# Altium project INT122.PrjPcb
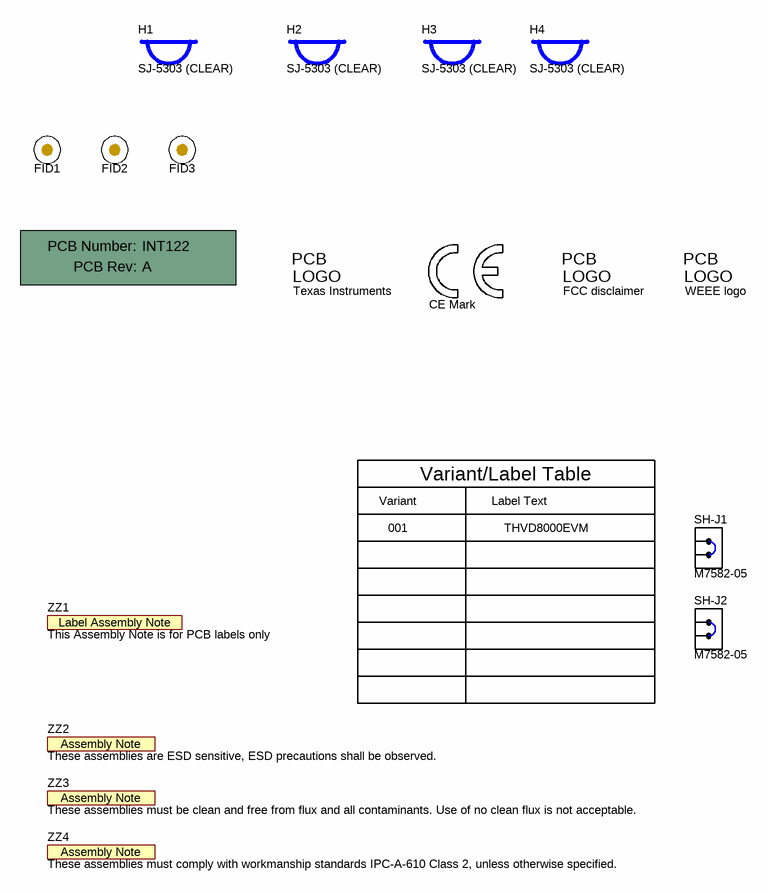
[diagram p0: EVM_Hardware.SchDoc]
CopyrightYear: 2020; PCB_Layout: A0866568; PCB_Rev: A; PRJ_Customer: Public Release; PRJ_Engineer: A0866568; PRJ_Number: INT122; PRJ_Title: THVD8000EVM; SCH_Rev: A; TechSupport: http://www.ti.com/support; TID: NA
2 sheets, 95 parts. Net scope: global (net labels, ports and power ports of the same name join across sheets).
Board file: INT122.PcbDoc
Sheets:
  EVM_Hardware.SchDoc
  INT122.SchDoc

## Sheet EVM_Hardware.SchDoc
size 431 x 279 mm; Date: Not shown in title block; ApprovedBy: Not shown in title block; CheckedBy: Not shown in title block; Author: Not shown in title block; CompanyName: Not shown in title block; Engineer: Not shown in title block; Organization: Not shown in title block; Address1: Not shown in title block; Address2: Not shown in title block; Address3: Not shown in title block; Address4: Not shown in title block; DocumentNumber: 1; Revision: Use project parameter SCH_Rev; SheetNumber: 1; SheetTotal: 2; PageSetup: Record=PageOptions¦CenterHorizontal=True¦CenterVertical=True¦PrintScale=1.00¦XCorrection=1.00¦YCorrection=1.00¦PrintKind=0¦BorderSize=5000000¦LeftOffset=0¦BottomOffset=0¦Orientation=2¦PaperLength=1000¦PaperWidth=1000¦Scale=100¦PaperSource=15¦PrintQuality=600¦MediaType=1¦DitherType=10¦PaperKind=Letter¦PrintScaleMode=1

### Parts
!PCB?  Printed Circuit Board  (value not drawn)  (mechanical)
FID1  Fiducial  [Fiducial10-20]  (value not drawn)
FID2  Fiducial  [Fiducial10-20]  (value not drawn)
FID3  Fiducial  [Fiducial10-20]  (value not drawn)
H1  SJ-5303 (CLEAR)  [Bumpon_SJ5003Transparent]
H2  SJ-5303 (CLEAR)  [Bumpon_SJ5003Transparent]
H3  SJ-5303 (CLEAR)  [Bumpon_SJ5003Transparent]
H4  SJ-5303 (CLEAR)  [Bumpon_SJ5003Transparent]
Logo1  Texas Instruments  [TI_Stacked_Overlay_Small]  (no BOM)
Logo2  CE Mark  [CE_Mark_5mm]  (no BOM)
Logo3  FCC disclaimer  [FCC_disclaimer]  (no BOM)
Logo4  WEEE logo  [WEEE_Minimum]  (no BOM)
SH-J1  M7582-05  [Harwin_M7582-05]
SH-J2  M7582-05  [Harwin_M7582-05]
ZZ1  This Assembly Note is for PCB labels only  [AssemblyNoteLabel]  (no BOM)
ZZ2  These assemblies are ESD sensitive, ESD precautions shall be observed.  [AssemblyNote]  (no BOM)
ZZ3  These assemblies must be clean and free from flux and all contaminants. Use of no clean flux is not acceptable.  [AssemblyNote]  (no BOM)
ZZ4  These assemblies must comply with workmanship standards IPC-A-610 Class 2, unless otherwise specified.  [AssemblyNote]  (no BOM)

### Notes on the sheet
- Variant
- Variant/Label Table
- Label Text
- 001
- THVD8000EVM

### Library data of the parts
!PCB? = CMP-0003618-2: Manufacturer: Any; PartNumber: INT122
FID1-FID3 = CMP-0077181-1: Fiducial mark.  There is nothing to buy or mount.
H1-H4 = CMP-0003620-1: Bumpon, Hemisphere, 0.44 X 0.20, Clear; Manufacturer: 3M
Logo1 = CMP-0074838-1: Texas Instrument Corporate Signature; SymbolCreator: a0412235; Lib Reference: TI_Logo; Library Reference: Logo
Logo2 = CMP-0074844-1: SymbolCreator: a0412235
Logo3 = CMP-0074847-1: FCC_disclaimer; Library Reference: Logo
Logo4 = CMP-0074769-1
SH-J1 SH-J2 = CMP-0078738-1: Single Operation 2.54mm Pitch Open Top Jumper Socket; Manufacturer: Harwin; CompType: Shunt
ZZ1 = CMP-0003616-3
ZZ2 = CMP-0077236-1
ZZ3 = CMP-0077237-1
ZZ4 = CMP-0077238-1

## Sheet INT122.SchDoc
size 431 x 279 mm; Date: Not shown in title block; ApprovedBy: Not shown in title block; CheckedBy: Not shown in title block; Author: Not shown in title block; CompanyName: Not shown in title block; Engineer: Not shown in title block; Organization: Not shown in title block; Address1: Not shown in title block; Address2: Not shown in title block; Address3: Not shown in title block; Address4: Not shown in title block; DocumentNumber: 1; Revision: Use project parameter SCH_Rev; SheetNumber: 2; SheetTotal: 2; PageSetup: Record=PageOptions¦CenterHorizontal=True¦CenterVertical=True¦PrintScale=1.00¦XCorrection=1.00¦YCorrection=1.00¦PrintKind=0¦BorderSize=5000000¦LeftOffset=0¦BottomOffset=0¦Orientation=2¦PaperLength=1000¦PaperWidth=1000¦Scale=100¦PaperSource=15¦PrintQuality=600¦MediaType=1¦DitherType=10¦PaperKind=Letter¦PrintScaleMode=1
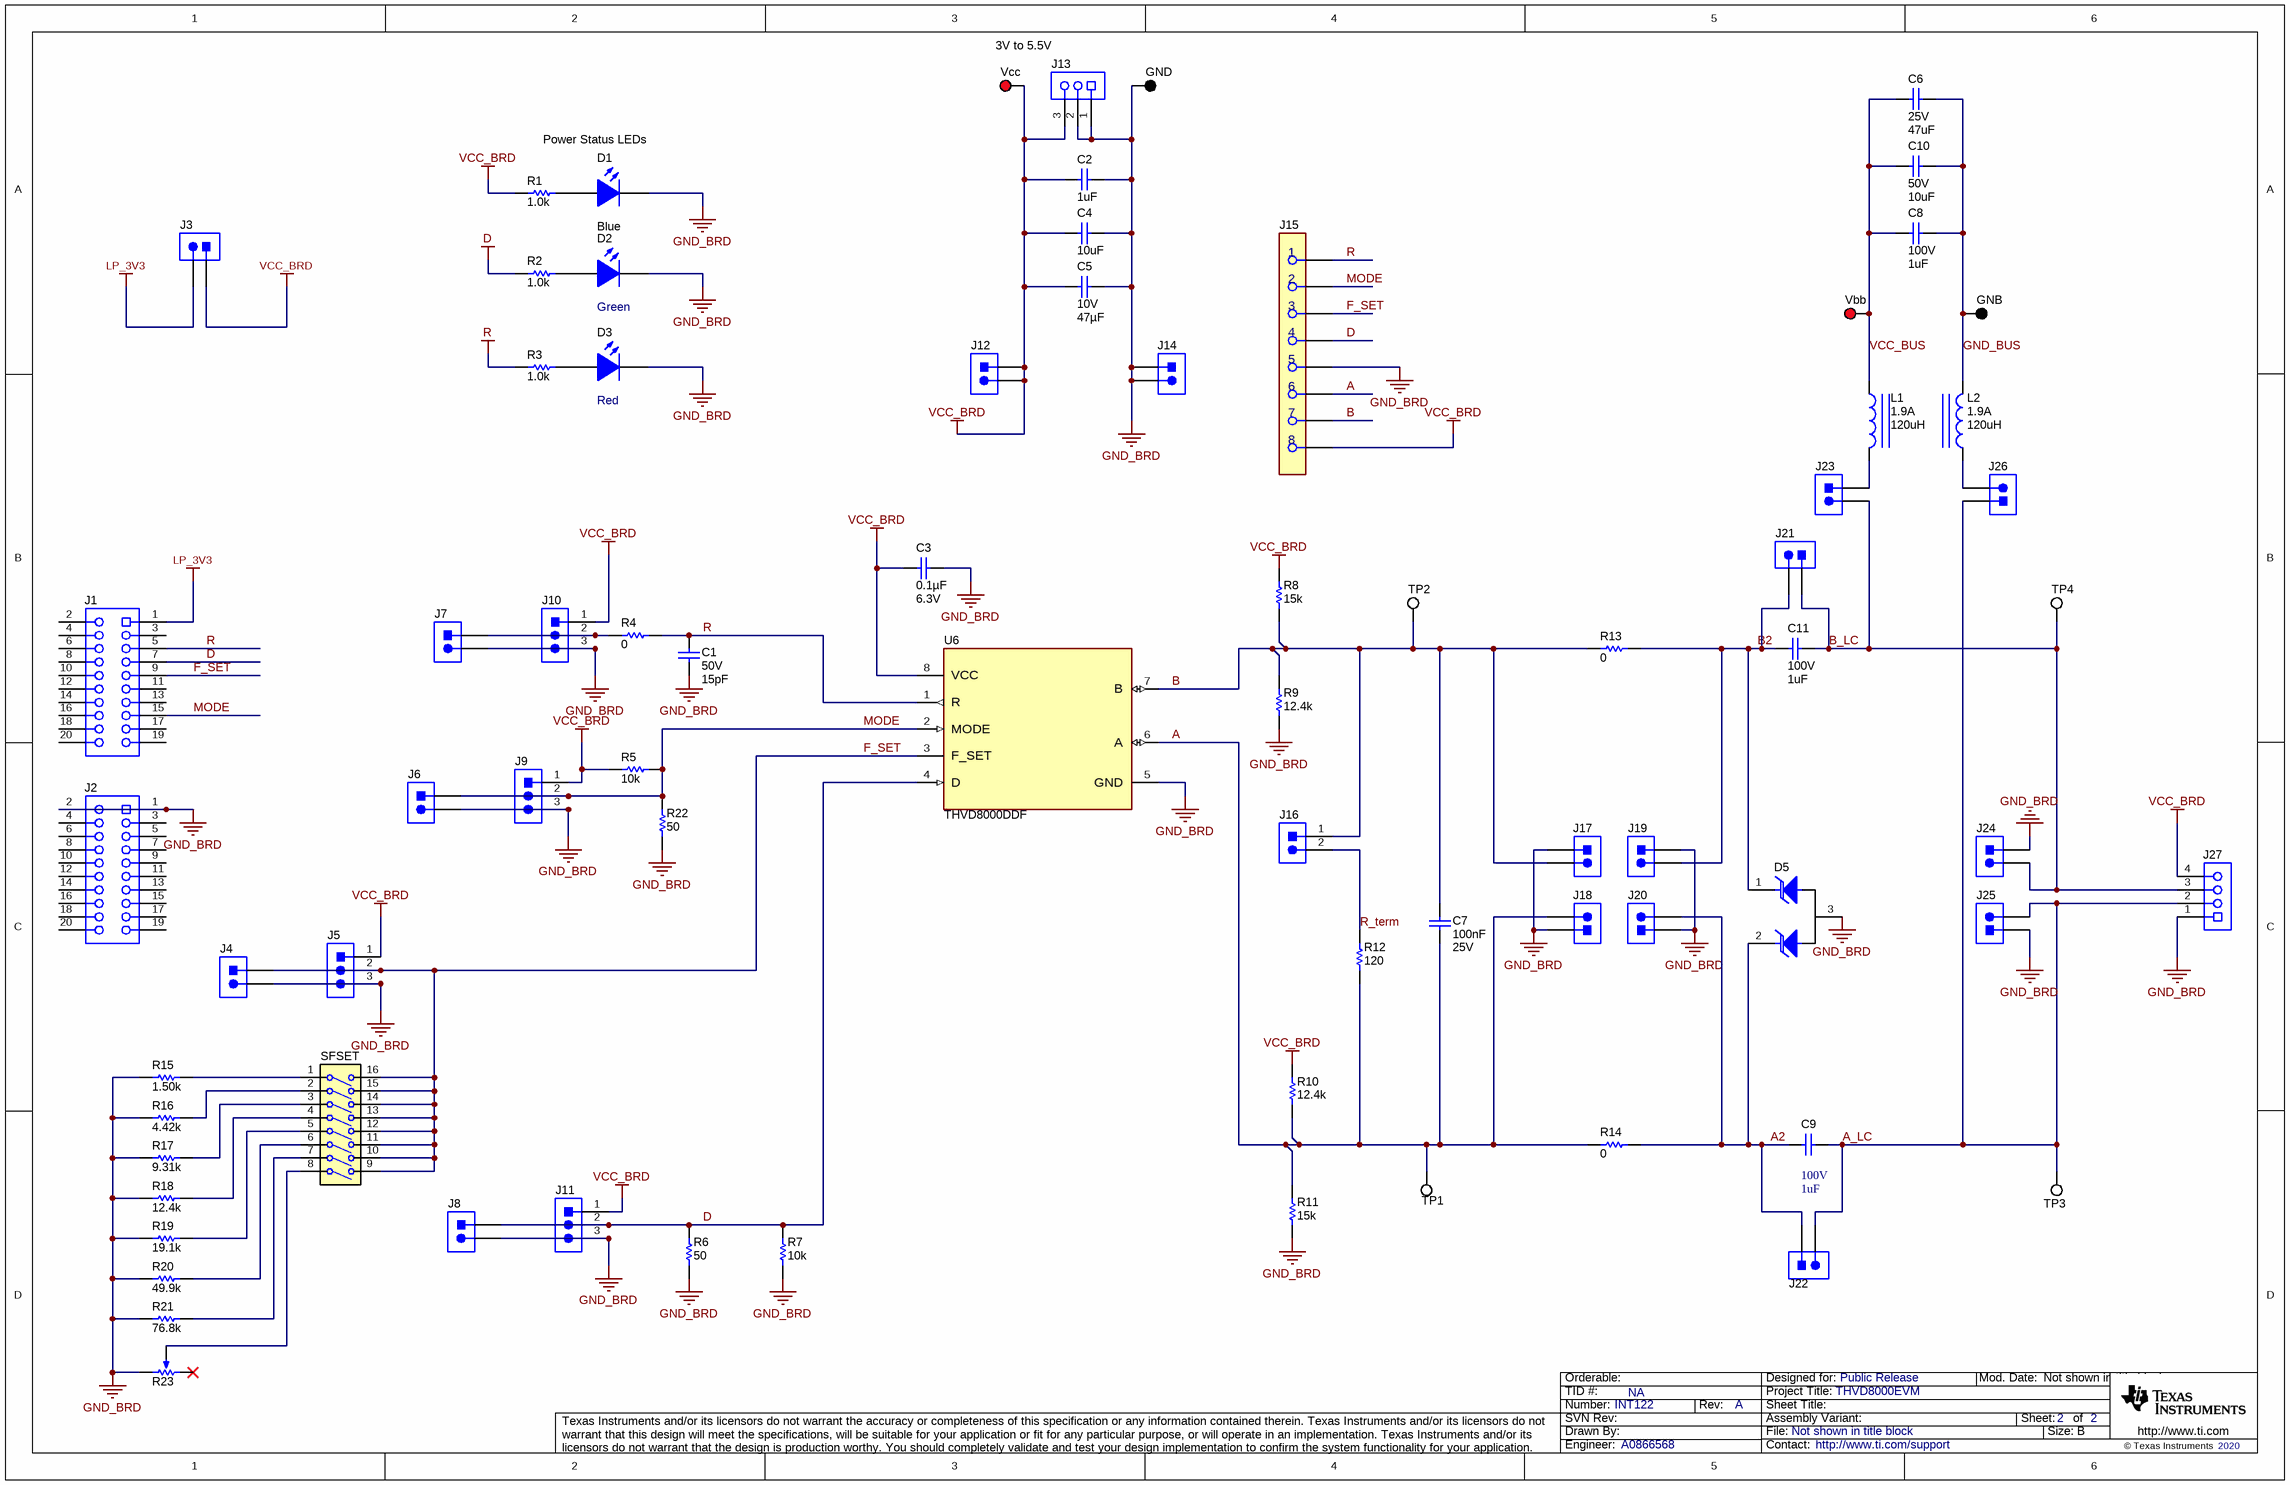
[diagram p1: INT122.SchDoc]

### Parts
C1  VDC_V: 50V  ValueDisplayed: 15pF  [0603]  (hidden comment: 06035A150JAT2A)
C2  ValueDisplayed: 1uF  [1206]  (hidden comment: 12063C105KAT2A)
C3  ValueDisplayed: 0.1µF  VDC_V: 6.3V  [0603]  (hidden comment: C0603C104K9PAC7867)
C4  ValueDisplayed: 10uF  [1206_180]  (hidden comment: C3216X7R1V106K160AC)
C5  VDC_V: 10V  ValueDisplayed: 47µF  [0805_HV]  (hidden comment: GRM21BR61A476ME15L)
C6  VDC_V: 25V  ValueDisplayed: 47uF  [1206_190]  (hidden comment: C3216X5R1E476M160AC)
C7  Cap_F: 100nF  VDC_V: 25V  [0805_HV]  (hidden comment: 08053C104KAT2A)
C8  VDC_V: 100V  ValueDisplayed: 1uF  [1206_180]  (hidden comment: CGA5L2X7R2A105K160AA)
C9  VDC_V: 100V  ValueDisplayed: 1uF  [1206_180]  (hidden comment: CGA5L2X7R2A105K160AA)
C10  VDC_V: 50V  ValueDisplayed: 10uF  [1206_180]  (hidden comment: CL31B106KBHNNNE)
C11  VDC_V: 100V  ValueDisplayed: 1uF  [1206_180]  (hidden comment: CGA5L2X7R2A105K160AA)
D1  value Blue  [WL-SMCW_Blue]  (hidden comment: 150060BS75000)
D2  value Green  [WL-SMCW_GREEN]  (hidden comment: 150060GS75000)
D3  value Red  [WL-SMCW_RED]  (hidden comment: 150060RS75000)
D5  CDSOT23-T12C  [SOT-23]  (value not drawn)
GNB  5011  [Keystone5011]  (value not drawn)
GND  5011  [Keystone5011]  (value not drawn)
J1  SSQ-110-23-F-D  [Samtec_SSQ-110-23-F-D]  (value not drawn)
J2  SSQ-110-23-F-D  [Samtec_SSQ-110-23-F-D]  (value not drawn)
J3  961102-6404-AR  [3M_961102-6404-AR]  (value not drawn)
J4  61300211121  [WURTH_61300211121]  (value not drawn)
J5  61300311121  [WURTH_61300311121]  (value not drawn)
J6  61300211121  [WURTH_61300211121]  (value not drawn)
J7  61300211121  [WURTH_61300211121]  (value not drawn)
J8  61300211121  [WURTH_61300211121]  (value not drawn)
J9  61300311121  [WURTH_61300311121]  (value not drawn)
J10  61300311121  [WURTH_61300311121]  (value not drawn)
J11  61300311121  [WURTH_61300311121]  (value not drawn)
J12  61300211121  [WURTH_61300211121]  (value not drawn)
J13  1725669  [Phoenix_1725669]  (value not drawn)
J14  61300211121  [WURTH_61300211121]  (value not drawn)
J15  SK02-0008SOP-GS-04A  [FP-SK02-0008SOP-GS-04A_SOCKET-MFG]  (value not drawn)
J16  961102-6404-AR  [3M_961102-6404-AR]  (value not drawn)
J17  61300211121  [WURTH_61300211121]  (value not drawn)
J18  61300211121  [WURTH_61300211121]  (value not drawn)
J19  61300211121  [WURTH_61300211121]  (value not drawn)
J20  61300211121  [WURTH_61300211121]  (value not drawn)
J21  961102-6404-AR  [3M_961102-6404-AR]  (value not drawn)
J22  961102-6404-AR  [3M_961102-6404-AR]  (value not drawn)
J23  961102-6404-AR  [3M_961102-6404-AR]  (value not drawn)
J24  61300211121  [WURTH_61300211121]  (value not drawn)
J25  61300211121  [WURTH_61300211121]  (value not drawn)
J26  961102-6404-AR  [3M_961102-6404-AR]  (value not drawn)
J27  ED120/4DS  [On-Shore_ED120_4DS]  (value not drawn)
L1  Value2: 1.9A  ValueDisplayed: 120uH  [MSS1278T]  (hidden comment: MSS1278T-124KLB)
L2  Value2: 1.9A  ValueDisplayed: 120uH  [MSS1278T]  (hidden comment: MSS1278T-124KLB)
R1  ValueDisplayed: 1.0k  [0603]  (hidden comment: CRCW06031K00JNEA)
R2  ValueDisplayed: 1.0k  [0603]  (hidden comment: CRCW06031K00JNEA)
R3  ValueDisplayed: 1.0k  [0603]  (hidden comment: CRCW06031K00JNEA)
R4  ValueDisplayed: 0  [0603]  (hidden comment: RCS06030000Z0EA)
R5  ValueDisplayed: 10k  [0603]  (hidden comment: RC1608J103CS)
R6  ValueDisplayed: 50  [0603]  (hidden comment: RCP0603W50R0GEB)
R7  ValueDisplayed: 10k  [0603]  (hidden comment: RC1608J103CS)
R8  ValueDisplayed: 15k  [0603]  (hidden comment: RC0603JR-0715KL)
R9  ValueDisplayed: 12.4k  [0603]  (hidden comment: RC0603FR-0712K4L)
R10  ValueDisplayed: 12.4k  [0603]  (hidden comment: RC0603FR-0712K4L)
R11  ValueDisplayed: 15k  [0603]  (hidden comment: RC0603JR-0715KL)
R12  ValueDisplayed: 120  [0805_HV]  (hidden comment: ERJ-P06J121V)
R13  ValueDisplayed: 0  [0603]  (hidden comment: RCS06030000Z0EA)
R14  ValueDisplayed: 0  [0603]  (hidden comment: RCS06030000Z0EA)
R15  ValueDisplayed: 1.50k  [0603]  (hidden comment: ERJ-3EKF1501V)
R16  ValueDisplayed: 4.42k  [0603]  (hidden comment: CRCW06034K42FKEA)
R17  ValueDisplayed: 9.31k  [0603]  (hidden comment: CRCW06039K31FKEA)
R18  ValueDisplayed: 12.4k  [0603]  (hidden comment: RC0603FR-0712K4L)
R19  ValueDisplayed: 19.1k  [0603]  (hidden comment: RC0603FR-0719K1L)
R20  ValueDisplayed: 49.9k  [0603]  (hidden comment: RC0603FR-0749K9L)
R21  ValueDisplayed: 76.8k  [0603]  (hidden comment: CRCW060376K8FKEA)
R22  ValueDisplayed: 50  [0603]  (hidden comment: RCP0603W50R0GEB)
R23  TC33X-2-103E  [Bourns_TC33X-2]  (value not drawn)
SFSET  1-1571983-1  [SW_1-1571983-1]  (value not drawn)
TP1  5012  [Keystone5012]  (value not drawn)
TP2  5012  [Keystone5012]  (value not drawn)
TP3  5012  [Keystone5012]  (value not drawn)
TP4  5012  [Keystone5012]  (value not drawn)
U6  THVD8000DDF  [DDF0008A-MFG]
Vbb  5010  [Keystone5010]  (value not drawn)
Vcc  5010  [Keystone5010]  (value not drawn)

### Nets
D: J1.7 J8.1 J11.2 J15.4 R2.1 R6.2 R7.2 U6.4(D)
GND_BRD: C1.2 C2.2 C3.1 C4.2 C5.1 D1.1(K) D2.1(K) D3.1(K) D5.3(A) GND.1 J2.1 J2.2 J4.2 J5.3 J6.2 J7.2 J8.2 J9.3 J10.3 J11.3 J13.1 J13.2 J14.1 J14.2 J15.5 J17.1 J18.1 J19.1 J20.1 J24.1 J25.1 J27.1 R6.1 R7.1 R9.1 R11.1 R15.1 R16.1 R17.1 R18.1 R19.1 R20.1 R21.1 R22.1 R23.3(CW) U6.5(GND)
LP_3V3: J1.1 J3.2
R: C1.1 J1.5 J15.1 R3.1 R4.2 U6.1(R)
VCC_BRD: C2.1 C3.2 C4.1 C5.2 J3.1 J5.1 J9.1 J10.1 J11.1 J12.1 J12.2 J13.3 J15.8 J27.4 R1.1 R5.2 R8.2 R10.2 U6.8(VCC) Vcc.1
A: C7.2 J15.6 J18.2 R10.1 R11.2 R12.1 R14.1 TP1.1 U6.6(A)
A2: C9.2 D5.2(C) J20.2 J22.1 R14.2
A_LC: C9.1 J22.2 J25.2 J26.1 J27.2 TP3.1
B: C7.1 J15.7 J16.1 J17.2 R8.1 R9.2 R13.1 TP2.1 U6.7(B)
B2: C11.2 D5.1(C) J19.2 J21.2 R13.2
B_LC: C11.1 J21.1 J23.2 J24.2 J27.3 TP4.1
F_SET: J1.9 J4.1 J5.2 J15.3 SFSET.9(8A) SFSET.10(7A) SFSET.11(6A) SFSET.12(5A) SFSET.13(4A) SFSET.14(3A) SFSET.15(2A) SFSET.16(1A) U6.3(F_SET)
GND_BUS: C6.1 C8.1 C10.1 GNB.1 L2.2
MODE: J1.15 J6.1 J9.2 J15.2 R5.1 R22.2 U6.2(MODE)
R_term: J16.2 R12.2
VCC_BUS: C6.2 C8.2 C10.2 L1.1 Vbb.1
NetD1_2: D1.2(A) R1.2
NetD2_2: D2.2(A) R2.2
NetD3_2: D3.2(A) R3.2
NetJ7_1: J7.1 J10.2 R4.1
NetJ23_1: J23.1 L1.2
NetJ26_2: J26.2 L2.1
NetR15_2: R15.2 SFSET.1
NetR16_2: R16.2 SFSET.2
NetR17_2: R17.2 SFSET.3
NetR18_2: R18.2 SFSET.4
NetR19_2: R19.2 SFSET.5
NetR20_2: R20.2 SFSET.6
NetR21_2: R21.2 SFSET.7
NetR23_2: R23.2(WIPER) SFSET.8

Not connected (* = marked no-connect by the designer): J1 2 3 4 6 8 10 11 12 13 14 16 17 18 19 20; J2 3 4 5 6 7 8 9 10 11 12 13 14 15 16 17 18 19 20; R23 1(CCW)*

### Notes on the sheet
- 3V to 5.5V
- Power Status LEDs

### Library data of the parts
C1 = CMP-0006767-4: CAP, CERM, 15 pF, 50 V, +/- 5%, C0G/NP0, 0603; Manufacturer: AVX; TaMin_C: -55°C; ESR_ohm: 3.2d; Polarized: N; SizeAreaWB_mm2: 4.68; Value1: 0.32 ohm; U/M: EA; Value: 15pF; TaMax_C: 125°C; SizeZ_mm: 1; SizeX_mm: 1.6; SizeY_mm: 0.8; SizeArea_mm2: 1.28; AEC Category: Q200
C2 = CMP-0008509-2: CAP, CERM, 1 uF, 25 V, +/- 10%, X7R, 1206; Manufacturer: AVX; TaMin_C: -55°C; ESR_ohm: 0.013; Polarized: N; SizeAreaWB_mm2: 10.92; Value1: 0.013 ohm; U/M: EA; Value: 1uF; TaMax_C: 125°C; SizeZ_mm: 1.35; SizeX_mm: 3.2; SizeY_mm: 1.6; Value2: 25V; SizeArea_mm2: 5.12; CompType: Capacitor; Cap_F: 1µF; AEC Category: Q200
C3 = CMP-0085846-1: CAP, CERM, 0.1 µF, 6.3 V,+/- 10%, X5R, 0603; Manufacturer: Kemet; SizeAreaWB_mm2: 4.68; SizeArea_mm2: 1.28; SizeZ_mm: 1; Polarized: N; Cap_F: 100nF; TaMin_C: -55°C; AEC Category: Q200; SizeX_mm: 1.6; Value: 0.1uF; U/M: EA; SizeY_mm: 0.8; TaMax_C: 85°C
C4 = CMP-0008705-2: CAP, CERM, 10 uF, 35 V, +/- 10%, X7R, 1206; Manufacturer: TDK; TaMin_C: -55°C; ESR_ohm: 2.229m; Polarized: N; SizeAreaWB_mm2: 10.92; Value1: 0.002229 ohm; U/M: EA; Value: 10uF; TaMax_C: 125°C; SizeZ_mm: 1.8; SizeX_mm: 3.2; SizeY_mm: 1.6; Value2: 35V; SizeArea_mm2: 5.12; CompType: Capacitor; Cap_F: 10µF; IRMS_A: 4.85932A; AEC Category: Q200
C5 = CMP-0078699-1: CAP, CERM, 47 µF, 10 V,+/- 20%, X5R, 0805; Manufacturer: MuRata; TaMin_C: -55°C; Polarized: N; Green_Lifecycle: Active; SizeAreaWB_mm2: 6.75; Green_REACh: Passed; U/M: EA; Value: 47uF; TaMax_C: 85°C; SizeZ_mm: 1.45; SizeX_mm: 2; SizeY_mm: 1.25; Cap_Case: 0805; SizeArea_mm2: 2.5; CompType: Capacitor; AEC Category: Q200
C6 = CMP-0008656-2: CAP, CERM, 47 uF, 25 V, +/- 20%, X5R, 1206_190; Manufacturer: TDK; TaMin_C: -55°C; Polarized: N; SizeAreaWB_mm2: 10.92; Value1: Unknown; U/M: EA; Value: 47uF; TaMax_C: 85°C; SizeZ_mm: 1.9; SizeX_mm: 3.2; SizeY_mm: 1.6; Cap_Case: 1206; SizeArea_mm2: 5.12; CompType: Capacitor; Cap_F: 47µF; AEC Category: Q200
C7 = CMP-0007567-2: CAP, CERM, 0.1 uF, 25 V, +/- 10%, X7R, 0805; Manufacturer: AVX; TaMin_C: -55°C; ESR_ohm: 2.8d; Polarized: N; SizeAreaWB_mm2: 6.75; Value1: 0.28 ohm; U/M: EA; Value: 0.1uF; TaMax_C: 125°C; SizeZ_mm: 1.45; SizeX_mm: 2; SizeY_mm: 1.25; Cap_Case: 0805; SizeArea_mm2: 2.5; AEC Category: Q200
C8 C9 C11 = CMP-0008779-2: CAP, CERM, 1 uF, 100 V, +/- 10%, X7R, AEC-Q200 Grade 1, 1206; Manufacturer: TDK; TaMin_C: -55°C; ESR_ohm: 4.575m; Polarized: N; SizeAreaWB_mm2: 10.92; Value1: 0.004575 ohm; U/M: EA; Value: 1uF; TaMax_C: 125°C; SizeZ_mm: 1.8; SizeX_mm: 3.2; SizeY_mm: 1.6; SizeArea_mm2: 5.12; CompType: Capacitor; AEC Qualified: Y; Cap_F: 1µF; IRMS_A: 3.39639A; AEC Grade: 1; AEC Category: Q200
C10 = CMP-0008802-2: CAP, CERM, 10 uF, 50 V, +/- 10%, X7R, 1206; Manufacturer: Samsung; TaMin_C: -55°C; Polarized: N; SizeAreaWB_mm2: 10.92; Value1: Unknown; U/M: EA; Value: 10uF; TaMax_C: 125°C; SizeZ_mm: 1.8; SizeX_mm: 3.2; SizeY_mm: 1.6; Cap_Case: 1206; SizeArea_mm2: 5.12; CompType: Capacitor; Cap_F: 10µF; AEC Category: Q200
D1 = CMP-0002946-3: LED, Blue, SMD; Manufacturer: Wurth Elektronik; Power_TotalModule: 105mW; Angle: 140; Tjmax_C: 85°C; Vf_V: 3.2V; Io_A: 30mA; Value1: 0.105W; Vr_V: 5V; Type: InGaN
D2 = CMP-0002905-2: LED, Green, SMD; Manufacturer: Wurth Elektronik; Io_A: 20mA; Tjmax_C: 85°C; Value1: W; Angle: 140; Vf_V: 3.2V; Type: InGaN
D3 = CMP-0002947-3: LED, Red, SMD; Manufacturer: Wurth Elektronik; Io_A: 30mA; Power_TotalModule: 72mW; Vr_V: 5V; Tjmax_C: 85°C; Value1: 0.072W; Angle: 140; Vf_V: 2V; Type: AlInGaP
D5 = CMP-0005918-3: Diode, TVS, Bi, 12 V, 25.9 Vc, SOT-23; Manufacturer: Bourns; SizeAreaWB_mm2: 14; Value1: 500W; Value: 12V; SizeZ_mm: 1.1; SizeX_mm: 2.5; SizeY_mm: 3; SizeArea_mm2: 7.5; AEC Qualified: N; AEC Category: Q101; Ipp: 21A; Vbr_Min: 13.3V; Vc: 25.9V
GNB GND = CMP-0055148-1: Test Point, Multipurpose, Black, TH; Manufacturer: Keystone; CNHeader: FALSE; Green_Lifecycle: Active; Green_REACh: Passed; ContactFinish: Silver; CT: TRUE
J1 J2 = CMP-0055675-1: Receptacle, 2.54mm, 10x2, Gold, TH; Manufacturer: Samtec; CNHeader: FALSE; Current_A: 6.3A; Gender: Female; Cert_CSA: Y; Voltage_V: 550V; CompType: Socket Strip; Row_Count: 2; RowSpacing_mm: 2.54; CT: TRUE
J3 J16 J21-J23 J26 = CMP-0075197-1: Header, 2.54mm, 2x1, TH; Manufacturer: 3M; CNHeader: True; Current_A: 2A; Green_Lifecycle: Active; Shrouded: N; Gender: Male; Green_REACh: Passed; Voltage_V: 1kV; Row_Count: 1; Pitch_mm: 2.54; ContactFinish: Gold; CT: False; Cert_UL: Y
J4 J6-J8 J12 J14 J17-J20 J24 J25 = CMP-0054794-2: Header, 2.54 mm, 2x1, Gold, TH; Manufacturer: Wurth Elektronik; Shrouded: N; Gender: Male; Green_REACh: Passed; Pitch_mm: 2.54; Green_Lifecycle: Active; Row_Count: 1; Cert_UL: Y
J5 J9-J11 = CMP-0054796-2: Header, 2.54 mm, 3x1, Gold, TH; Manufacturer: Wurth Elektronik; Pitch_mm: 2.54; Green_Lifecycle: Active; Cert_UL: Y; Shrouded: N; Green_REACh: Passed; Gender: Male; Row_Count: 1
J13 = CMP-0055500-1: Terminal Block, 3x1, 2.54 mm, TH; Manufacturer: Phoenix Contact; CNHeader: FALSE; Green_Lifecycle: Not Set; Green_REACh: Incomplete; CT: TRUE
J15 = CMP-0088168-1: CUSTOM SOCKET FOR 1.6X2.9X1.1mm DEVICE, DDF PACKAGE, 0.65mm PITCH, HIGH SPEED SPRING PROBES POGO-1300; Manufacturer: RST; Symbol Name: SYM-SK02-0008SOP-GS-04A; SizeZ_mm: 37.2762mm; DUT-PIN: 8; DUT-PackageType: SOT23-8
J27 = CMP-0074939-1: Terminal Block, 5.08 mm, 4x1, Brass, TH; Manufacturer: On-Shore Technology; Cert_VDE: Y; CNHeader: False; Current_A: 15A; Green_Lifecycle: Not Set; Shrouded: N; Gender: Female; Green_REACh: Incomplete; Voltage_V: 300V; Row_Count: 1; Pitch_mm: 5.08; CT: True
L1 L2 = CMP-0061931-2: Inductor, Shielded Drum Core, Ferrite, 120 uH, 1.9 A, 0.18 ohm, SMD; Manufacturer: Coilcraft; Isat: 3.58A @ 30% inductance drop; Irms: 1.9A @ 40C rise; Green_Lifecycle: Not Set; SizeAreaWB_mm2: 196; DCR_ohm: 1.8d; Green_REACh: Incomplete; Value: 120uH; SizeZ_mm: 8; SizeX_mm: 12; SizeArea_mm2: 144; Ind_H: 120µH; AEC Category: Q200
R1-R3 = CMP-0025729-4: RES, 1.0 k, 5%, 0.1 W, AEC-Q200 Grade 0, 0603; Manufacturer: Vishay-Dale; Power_W: 100mW; TempCo: 200 ppm/C; Value_Code: 1k00; Value: 1.0k; EIA_Code: E24; Res_ohm: 1k; SizeX_mm: 1.6; SizeY_mm: 0.8; SizeZ_mm: 1; Value2: 0.1W; SizeArea_mm2: 1.28; AEC Qualified: Y; VDC_V: 75V; AEC Category: Q200; AEC Grade: 0
R4 R13 R14 = CMP-0081973-1: RES, 0, 0%, 0.25 W, AEC-Q200 Grade 0, 0603; Manufacturer: Vishay-Dale; SizeAreaWB_mm2: 4.68; SizeArea_mm2: 1.28; AEC Qualified: Y; AEC Category: Q200; Value: 0; SizeZ_mm: 1; SizeY_mm: 0.8; Power_W: 250mW; Value2: 0.25W; SizeX_mm: 1.6
R5 R7 = CMP-0025945-3: RES, 10 k, 5%, 0.1 W, 0603; Manufacturer: Samsung Electro-Mechanics; Power_W: 100mW; TempCo: 100 ppm/C; Value_Code: 10k0; U/M: EA; Value: 10k; EIA_Code: E24; SizeX_mm: 1.6; SizeY_mm: 0.8; SizeZ_mm: 1; Value2: 0.1W; SizeArea_mm2: 1.28; AEC Qualified: N; VDC_V: 31V; AEC Category: Q200
R6 R22 = CMP-0082504-1: RES, 50, 2%, 3.9 W, 0603; Manufacturer: Vishay-Dale; Value_Code: 50R0; SizeAreaWB_mm2: 4.68; SizeArea_mm2: 1.28; AEC Qualified: N; AEC Category: Q200; Value: 50; SizeZ_mm: 1; TempCo: 150 ppm/C; Power_W: 3.9W; SizeY_mm: 0.8; SizeX_mm: 1.6
R8 R11 = CMP-0025890-5: RES, 15 k, 5%, 0.1 W, 0603; Manufacturer: Yageo; Power_W: 100mW; TempCo: 100 ppm/C; Value_Code: 15k0; Value: 15k; EIA_Code: E24; SizeX_mm: 1.6; SizeY_mm: 0.8; SizeZ_mm: 1; Value2: 0.1W; SizeArea_mm2: 1.28; AEC Qualified: N; VDC_V: 75V; AEC Category: Q200; SizeAreaWB_mm2: 4.68
R9 R10 = CMP-0022777-5: RES, 12.4 k, 1%, 0.1 W, 0603; Manufacturer: Yageo; Power_W: 100mW; TempCo: 100 ppm/C; Value_Code: 12k4; Value: 12.4k; EIA_Code: E96; SizeX_mm: 1.6; SizeY_mm: 0.8; SizeZ_mm: 1; Value2: 0.1W; SizeArea_mm2: 1.28; CompType: Resistor; AEC Qualified: N; VDC_V: 75V; AEC Category: Q200; SizeAreaWB_mm2: 4.68
R12 = CMP-0020795-2: RES, 120, 5%, 0.5 W, 0805; Manufacturer: Panasonic; Power_W: 500mW; TempCo: 200 ppm/C; Value_Code: 120R; U/M: EA; Value: 120; EIA_Code: E24; SizeX_mm: 2; SizeY_mm: 1.25; SizeZ_mm: 1.45; Value2: 0.5W; SizeArea_mm2: 2.5; VDC_V: 400V; AEC Category: Q200
R15 = CMP-0022689-3: RES, 1.50 k, 1%, 0.1 W, 0603; Manufacturer: Panasonic; Power_W: 100mW; TempCo: 100 ppm/C; Value_Code: 1k50; U/M: EA; Value: 1.50k; EIA_Code: E96; Res_ohm: 1.5k; SizeX_mm: 1.6; SizeY_mm: 0.8; SizeZ_mm: 1; Value2: 0.1W; SizeArea_mm2: 1.28; VDC_V: 75V; AEC Category: Q200
R16 = CMP-0022453-4: RES, 4.42 k, 1%, 0.1 W, AEC-Q200 Grade 0, 0603; Manufacturer: Vishay-Dale; Power_W: 100mW; TempCo: 100 ppm/C; Value_Code: 4k42; Value: 4.42k; EIA_Code: E96; SizeX_mm: 1.6; SizeY_mm: 0.8; SizeZ_mm: 1; Value2: 0.1W; SizeArea_mm2: 1.28; AEC Qualified: Y; VDC_V: 75V; AEC Category: Q200; AEC Grade: 0
R17 = CMP-0022666-4: RES, 9.31 k, 1%, 0.1 W, AEC-Q200 Grade 0, 0603; Manufacturer: Vishay-Dale; Power_W: 100mW; TempCo: 100 ppm/C; Value_Code: 9k31; Value: 9.31k; EIA_Code: E96; SizeX_mm: 1.6; SizeY_mm: 0.8; SizeZ_mm: 1; Value2: 0.1W; SizeArea_mm2: 1.28; AEC Qualified: Y; VDC_V: 75V; AEC Category: Q200; AEC Grade: 0
R18 = CMP-0022777-5: RES, 12.4 k, 1%, 0.1 W, 0603; Manufacturer: Yageo; Power_W: 100mW; TempCo: 100 ppm/C; Value_Code: 12k4; Value: 12.4k; EIA_Code: E96; SizeX_mm: 1.6; SizeY_mm: 0.8; SizeZ_mm: 1; Value2: 0.1W; SizeArea_mm2: 1.28; AEC Qualified: N; VDC_V: 75V; AEC Category: Q200; SizeAreaWB_mm2: 4.68
R19 = CMP-0022860-5: RES, 19.1 k, 1%, 0.1 W, 0603; Manufacturer: Yageo; Power_W: 100mW; TempCo: 100 ppm/C; Value_Code: 19k1; Value: 19.1k; EIA_Code: E96; SizeX_mm: 1.6; SizeY_mm: 0.8; SizeZ_mm: 1; Value2: 0.1W; SizeArea_mm2: 1.28; AEC Qualified: N; VDC_V: 75V; AEC Category: Q200; SizeAreaWB_mm2: 4.68
R20 = CMP-0023142-5: RES, 49.9 k, 1%, 0.1 W, 0603; Manufacturer: Yageo; Power_W: 100mW; TempCo: 100 ppm/C; Value_Code: 49k9; Value: 49.9k; EIA_Code: E96; SizeX_mm: 1.6; SizeY_mm: 0.8; SizeZ_mm: 1; Value2: 0.1W; SizeArea_mm2: 1.28; AEC Qualified: N; VDC_V: 75V; AEC Category: Q200; SizeAreaWB_mm2: 4.68
R21 = CMP-0022593-4: RES, 76.8 k, 1%, 0.1 W, AEC-Q200 Grade 0, 0603; Manufacturer: Vishay-Dale; Power_W: 100mW; TempCo: 100 ppm/C; Value_Code: 76k8; Value: 76.8k; EIA_Code: E96; SizeX_mm: 1.6; SizeY_mm: 0.8; SizeZ_mm: 1; Value2: 0.1W; SizeArea_mm2: 1.28; AEC Qualified: Y; VDC_V: 75V; AEC Category: Q200; AEC Grade: 0
R23 = CMP-0065392-2: TRIMMER 10K OHM 0.1W; Manufacturer: Bourns; SizeAreaWB_mm2: 22.08; SizeZ_mm: 1.5; SizeX_mm: 3.8; SizeY_mm: 3.6; SizeArea_mm2: 13.68; CompType: Potentiometer
SFSET = CMP-0065297-1: Switch, 8SPST, 0.025 A, 24 VDC, SMD; Manufacturer: TE Connectivity; CurrentRating_mA: 25A; SizeAreaWB_mm2: 134.5264; Circuit: SPST; PositionCount: 8.0; SizeZ_mm: 2.31; SizeX_mm: 8.13; SizeY_mm: 11.28; SizeArea_mm2: 91.7064; VDC_V: 24V
TP1-TP4 = CMP-0055149-1: Test Point, Multipurpose, White, TH; Manufacturer: Keystone; CNHeader: FALSE; Green_Lifecycle: Active; Green_REACh: Passed; ContactFinish: Silver; CT: TRUE
U6 = CMP-0088703-2: RS-485 Transceiver with OOK Modulation for Power Line Communication; Manufacturer: Texas Instruments; Number Of Receivers: 1; TaMin_C: -40°C; TJmax_C: +150°C; TaMax_C: +125°C; Data Rate: 10Mbits/s; SizeZ_mm: 1.1mm; AEC Qualified: No; Max Supply Voltage: 5.5V; Standoff Height: 0mm; AEC Category: Q200; CompType: IC; Min Supply Voltage: 3V; Simplex Duplex: Half-Duplex; Nominal Supply Current: 1.3-3.2mA
Vbb Vcc = CMP-0055147-1: Test Point, Multipurpose, Red, TH; Manufacturer: Keystone; CNHeader: FALSE; Green_Lifecycle: Active; Green_REACh: Passed; ContactFinish: Silver; CT: TRUE

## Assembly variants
001: not fitted C1 C7 FID1 FID2 FID3 JC_A JC_B JS R12 R13 R25 R26 R27 R28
